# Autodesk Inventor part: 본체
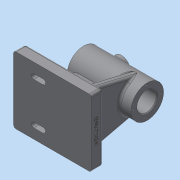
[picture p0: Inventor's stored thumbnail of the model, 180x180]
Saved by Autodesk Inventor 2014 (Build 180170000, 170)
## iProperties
Created: 2026-09
Part Number: 본체
Material: 일반
Document SubType Name: Modeling
Designer: dg
Density: 1 g/cm^3
Appearance: 기본값
Mass: 234.171 g
Surface Area: 514.68 cm^2
Volume: 234.171 cm^3
Author: dg
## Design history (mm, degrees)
sketch "스케치1"
  geometry: L1 (-41, 0)-(41, 0); L2 (-41, 14.5)-(21, 14.5); L3 (21, 14.5)-(21, 12.5); L4 (21, 12.5)-(41, 12.5); L5 (41, 12.5)-(41, 21); L6 (41, 21)-(-41, 21); L7 (-41, 21)-(-41, 14.5); 2 further points
  constraints: 14 end point, 5 parallel, 2 vertical alignment, 1 coincident, 1 horizontal, 1 midpoint, 1 perpendicular
  dimensions: "d0" = 82 distance of L1.start L1.end; "d1" = 25 diameter of L4 L1; "d2" = 29 diameter of L2 L1; "d3" = 42 diameter of L6 L1; "d4" = 62 distance between parallel lines of L3 L7
revolve "회전1" sketch "스케치1" stored, may be unused: angle "d5" = 90 deg
node "작업 평면1"
sketch "스케치2"
  geometry: L1 (41, 21)-(41, -21) reference; L2 (-41, 21)-(-41, -21) reference; L3 (59, -43)-(-41, -43); L4 (-41, -43)-(-41, 43); L5 (-41, 43)-(59, 43); L6 (59, 43)-(59, -43); 2 further points
  constraints: 8 end point, 2 midpoint, 2 parallel, 1 horizontal, 1 perpendicular
  dimensions: "d7" = 100 distance of L3.start L3.end; "d8" = 86 distance of L5.end L3.start
extrude "돌출1" join sketch "스케치2" distance "d9" = 15; taper "d10" = 0 deg
node "작업 평면2"
sketch "스케치3"
  geometry: L1 (41, 21)-(41, -21) reference; C1 r 11 at (16, 0); 1 further point
  constraints: 1 centre point, 1 horizontal alignment
  dimensions: "d12" = 22 diameter of C1; "d13" = 25 distance from line of C1.centre L1
extrude "돌출2" join sketch "스케치3" stored distance "d14" = 15; taper "d15" = 0 deg
hole "구멍1" diameter "d18" = 4.917; stored, may be unused: countersink angle "d22" = 90 deg, drill point angle "d24" = 118 deg; dims "d19" = 10, "d20" = 14, "d21" = 4, "d23" = 8, "d25" = 10, "d26" = 10
node "작업 평면3"
sketch "스케치4"
  geometry: L1 (86, 0)-(0, 0) reference; L2 (86, 0)-(86, 15) reference; L3 (0, 15)-(86, 15) reference; L4 (0, 0)-(0, 15) reference; L5 (22.559, 76.814)-(8, 15); L6 (63.441, 76.814)-(78, 15); C1 r 12.5 at (43, 72) reference; C2 r 21 at (43, 72) reference; A1 r 21 centre (43, 72) between (22.559, 76.814) and (63.441, 76.814) reference; 1 further point
  constraints: 4 end point, 2 point on circle, 2 point on line, 2 tangent
  dimensions: "d30" = 8 distance from line of L4 L5.end; "d31" = 8 distance from line of L6.end L2
extrude "돌출3" join sketch "스케치4" distance "d32" = 10; taper "d33" = 0 deg
sketch "스케치5"
  geometry: L1 (-41, 21)-(-27, 21) reference; L2 (-27, 21)-(-27, 24) reference; L3 (-27, 24)-(-23, 24) reference; L4 (-23, 24)-(-23, 20) reference; L5 (-23, 20)-(-18.458, 20) reference; L6 (-18.458, 20)-(-18.458, 14.5) reference; L7 (-18.458, 14.5)-(-41, 14.5) reference; L8 (-41, 14.5)-(-41, 21) reference; L9 (-5, 21)-(41, 21) reference; L10 (41, 21)-(41, 12.5) reference; L11 (41, 12.5)-(21, 12.5) reference; L12 (21, 12.5)-(21, 14.5) reference; L13 (21, 14.5)-(-13.541, 14.5) reference; L14 (-13.541, 14.5)-(-13.541, 20) reference; L15 (-13.541, 20)-(-9, 20) reference; L16 (-9, 20)-(-9, 24) reference; L17 (-9, 24)-(-5, 24) reference; L18 (-5, 24)-(-5, 21) reference; L19 (-41, -14.5)-(21, -14.5) reference; L20 (21, -14.5)-(21, -12.5) reference; L21 (21, -12.5)-(41, -12.5) reference; L22 (41, -12.5)-(41, -21) reference; L23 (41, -21)-(26, -21) reference; L24 (26, -21)-(26, -57) reference; L25 (26, -57)-(41, -57) reference; L26 (41, -57)-(41, -72) reference; L27 (41, -72)-(-59, -72) reference; L28 (-59, -72)-(-59, -57) reference; L29 (-59, -57)-(16, -57) reference; L30 (16, -57)-(16, -21) reference; L31 (16, -21)-(-41, -21) reference; L32 (-41, -21)-(-41, -14.5) reference; L33 (-44, -57)-(-30.897, -21); 1 further point
  constraints: 2 end point, 2 point on line
  dimensions: "d34" = 15 distance from line of L33.start L28; "d35" = 70 deg angle of L29 L33
feature "리브1" sketch "스케치5" dims "d36" = 1, "d37" = 10, "d38" = 0, "d39" = 0, "d40" = 1, "d41" = 1
sketch "스케치6"
  geometry: C1 r 14.5 at (0, 0) reference; 1 further point
  constraints: 1 vertical alignment
  dimensions: "d42" = 18 distance of point (0, 18) C1.centre
hole "구멍2" sketch "스케치6" at (0, 18) diameter "d43" = 2.459; stored, may be unused: countersink angle "d47" = 90 deg, drill point angle "d49" = 118 deg; dims "d44" = 8, "d45" = 14, "d46" = 4, "d48" = 10
chamfer "모따기1" distance "d53" = 1; stored, may be unused: second distance "d54" = 2, angle "d55" = 45 deg
sketch "스케치7"
  geometry: L1 (41, 43)-(-59, 43) reference; L2 (-59, 43)-(-59, -43) reference; L3 (-33, -27)-(-21, -27); L4 (-33, -34)-(-21, -34); L5 (-21, -20)-(-33, -20); L6 (-33, 27)-(-21, 27); L7 (-33, 20)-(-21, 20); L8 (-21, 34)-(-33, 34); L9 (-33, 30.3)-(-21, 30.3); L10 (-21, 23.7)-(-33, 23.7); L11 (-33, -23.7)-(-21, -23.7); L12 (-21, -30.3)-(-33, -30.3); A1 r 7 centre (-33, -27) between (-33, -20) and (-33, -34); A2 r 7 centre (-21, -27) between (-21, -34) and (-21, -20); A3 r 7 centre (-33, 27) between (-33, 34) and (-33, 20); A4 r 7 centre (-21, 27) between (-21, 20) and (-21, 34); A5 r 3.3 centre (-21, 27) between (-21, 23.7) and (-21, 30.3); A6 r 3.3 centre (-33, 27) between (-33, 30.3) and (-33, 23.7); A7 r 3.3 centre (-21, -27) between (-21, -30.3) and (-21, -23.7); A8 r 3.3 centre (-33, -27) between (-33, -23.7) and (-33, -30.3); 3 further points
  constraints: 24 end point, 16 point on circle, 8 centre point, 8 tangent, 7 parallel, 2 equal radius, 2 midpoint, 1 vertical alignment, 6 other
  dimensions: "d56" = 27 horizontal distance of point (-27, 27) point (0, 0); "d57" = 27 horizontal distance of point (-27, -27) point (0, 0); "d58" = 12 distance of L6.start L6.end; "d59" = 14 distance between parallel lines of L7 L8; "d60" = 26 distance from line of L3.start L2; "d61" = 6.6 distance between parallel lines of L10 L9
extrude "돌출4" join sketch "스케치7" distance "d62" = 3; taper "d63" = 0 deg
extrude "돌출5" cut sketch "스케치7" stored distance "d64" = 3; taper "d65" = 0 deg
sketch "스케치8"
  geometry: L1 (86, 0)-(0, 0) reference; 2 further points
  constraints: 1 vertical alignment, 1 other
  dimensions: "d67" = 6 distance from line of point (43, 6) L1
extrude "돌출6" join sketch "스케치8" distance "d68" = 0.5; taper "d69" = 0 deg
fillet "모깎기1" dims "d70" = 3
fillet "모깎기2" dims "d71" = 3
fillet "모깎기3" dims "d72" = 3
fillet "모깎기4" dims "d73" = 3
fillet "모깎기5" dims "d74" = 3
fillet "모깎기6" dims "d75" = 3
node "솔리드1"
pattern_circular "원형 패턴1" dims angle "d51" = 360 deg
mirror "대칭1"
node "투영된 루프1"
node "투영된 루프2"
node "투영된 루프3"
node "절단 모서리 투영1"
other parameters: "d6" = -72, "d11" = 24, "d27" = -15
